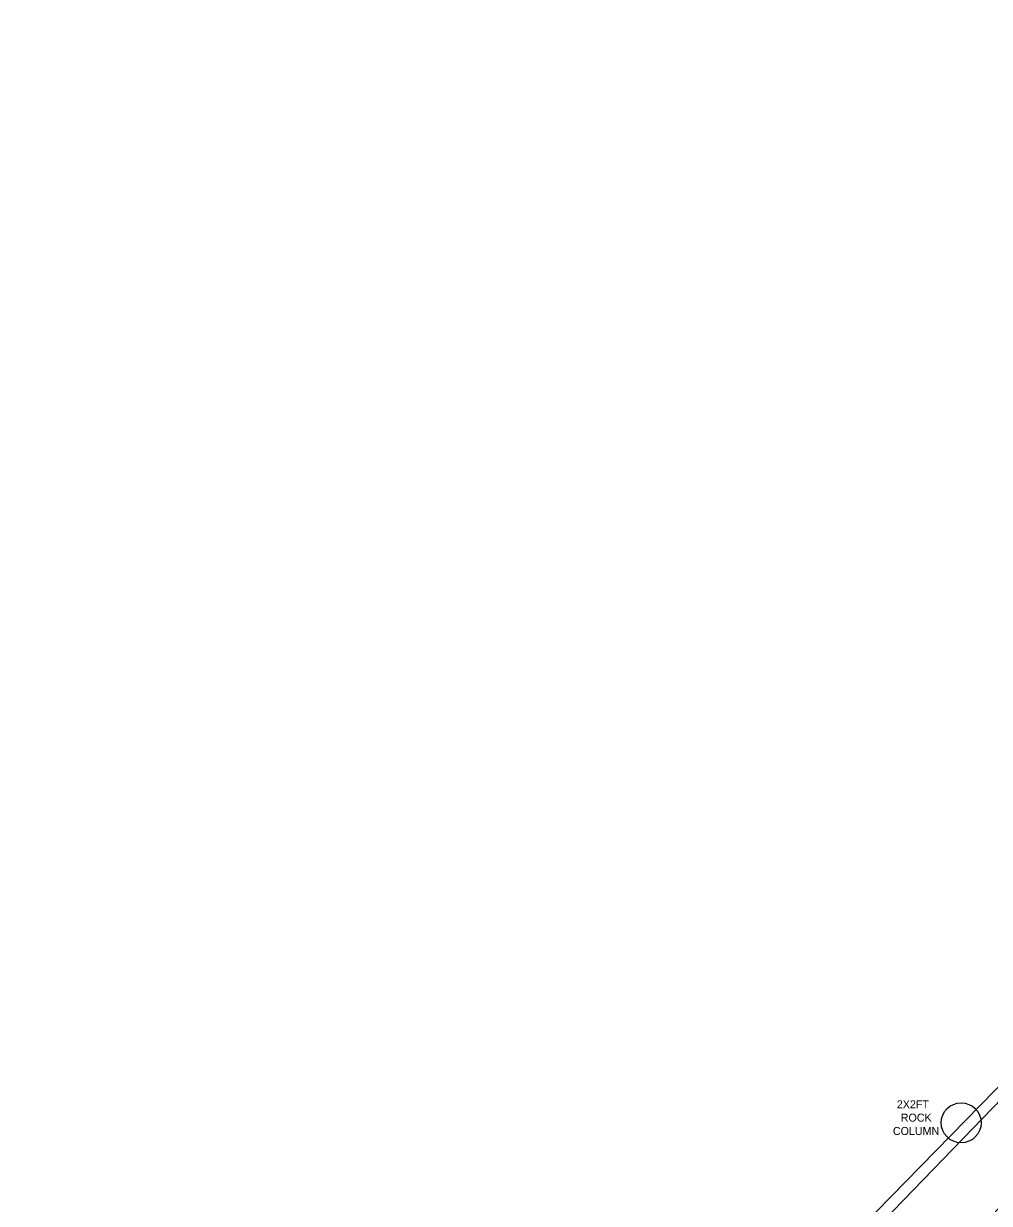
# Model space of a CAD drawing. Extents: x 2250985 to 2256614, y 13788366 to 13792478.
# Drawn here: x 2253199.8 to 2253344.7, y 13789214.4 to 13789391.3 of the extents above; entities that cross this region are included whole.
import ezdxf

# ---------------------------------------------------------------- set-up
doc = ezdxf.new("R2010")
doc.units = 0
for name, color, linetype in [('Bridge_Cap_Rebar', 7, 'Continuous'), ('Bridge_Cap_Stirrups', 7, 'Continuous'), ('Bridge_Column', 7, 'Continuous'), ('E_Geom_SurveyControl', 7, 'Continuous'), ('E_ROW_Driveway_3D_R', 7, 'Continuous'), ('E_Struc_Misc', 7, 'Continuous'), ('E_Terrain_Triangle_Vertices', 7, 'Continuous')]:
    doc.layers.add(name, color=color, linetype=linetype)

# ---------------------------------------------------------------- blocks, each defined once
blk = doc.blocks.new('COL')
at = {"layer": 'E_Geom_SurveyControl'}
blk.add_circle((0, 0), 0.3, dxfattribs=at)

msp = doc.modelspace()

# ---------------------------------------------------------------- linework, layer by layer
at = {"layer": 'E_ROW_Driveway_3D_R'}
msp.add_lwpolyline([(2253244.99, 13789117.2), (2253247.51, 13789128.31), (2253276.75, 13789157.96), (2253351.06, 13789234.82), (2253426.06, 13789311.4), (2253497.61, 13789385.21), (2253551.5, 13789439.88), (2253563.26, 13789449.89), (2253572.13, 13789466.79), (2253568.44, 13789486.16), (2253558.73, 13789495.84), (2253552.66, 13789494.83), (2253548.2, 13789491.86)], dxfattribs=at)
for points in [[(2253258.7, 13789125.01), (2253285.19, 13789150.8), (2253358.83, 13789226.99), (2253433.23, 13789304.07), (2253504.79, 13789378.92), (2253542.21, 13789416.41), (2253558.99, 13789436.05)], [(2253199.79, 13789023.57), (2253231.26, 13789055.67), (2253305.08, 13789131.6), (2253378.64, 13789207.45), (2253453.2, 13789283.87)]]:
    msp.add_spline(points, degree=3, dxfattribs=at)
at = {"layer": 'E_Struc_Misc'}
msp.add_lwpolyline([(2253248.77, 13789132.2), (2253276.19, 13789160.46), (2253350.01, 13789235.98), (2253424.99, 13789312.95), (2253496.37, 13789386.32), (2253548.6, 13789439.77)], dxfattribs=at)

# ---------------------------------------------------------------- block references
at = {"layer": 'E_Geom_SurveyControl', "xscale": 10, "yscale": 10}
msp.add_blockref('COL', (2253340.43, 13789226.47), dxfattribs=at)

# ---------------------------------------------------------------- texts
at = {"layer": 'Bridge_Cap_Rebar'}
msp.add_text('5737', height=0.06, dxfattribs=at).set_placement((2253340.58, 13789226.62))
at = {"layer": 'Bridge_Cap_Stirrups'}
msp.add_text('667.62', height=0.06, dxfattribs=at).set_placement((2253340.58, 13789226.26))
at = {"layer": 'Bridge_Column'}
msp.add_text('2X2 SQUARE COLUMN', height=0.06, dxfattribs=at).set_placement((2253340.58, 13789226.44))
at = {"layer": 'E_Terrain_Triangle_Vertices'}
for s, p in [('2X2FT ', (2253330.78, 13789228.64)), ('ROCK ', (2253331.37, 13789226.64)), ('COLUMN', (2253330.19, 13789224.64))]:
    msp.add_text(s, height=1.2, dxfattribs=at).set_placement(p)

doc.saveas('drawing.dxf')
